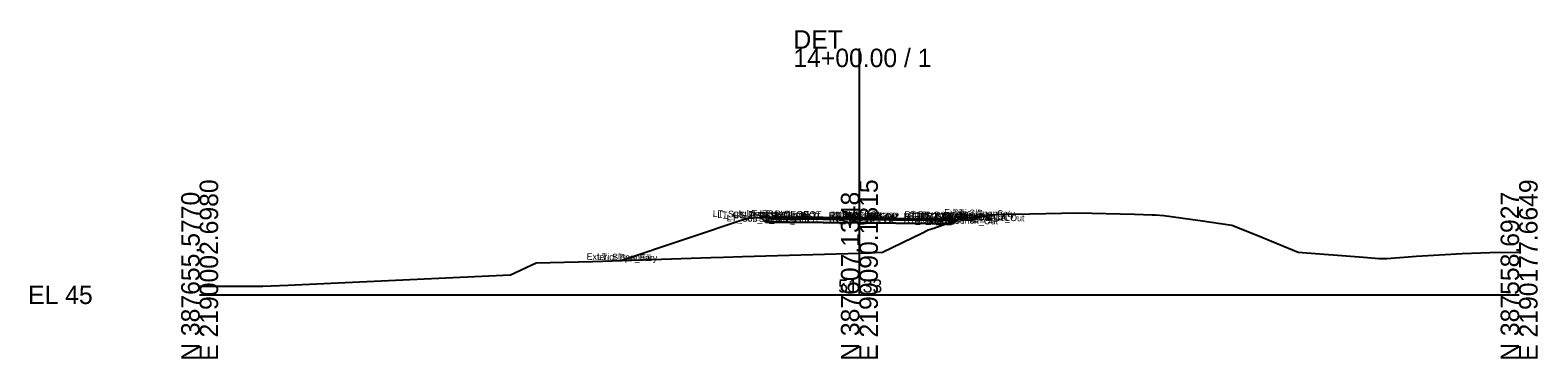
# Model space of a CAD drawing. Extents: x -26 to 1203, y -10 to 9543.
# Drawn here: x -25.7 to 202.8, y 3990.3 to 4040.1 of the extents above; entities that cross this region are included whole.
import ezdxf

# ---------------------------------------------------------------- set-up
doc = ezdxf.new("R2010")
doc.units = 0
for name, color, linetype in [('Default', 7, 'Continuous'), ('Exist Cross Section Cell', 7, 'Continuous'), ('Exist XS Center Line Elevation Label', 7, 'Continuous'), ('Exist XS Ground Line', 7, 'Continuous'), ('Prop CMT Pvmt Course 1', 7, 'Continuous'), ('Prop CMT Pvmt Course 2', 7, 'Continuous'), ('Prop CMT Pvmt Course 3', 7, 'Continuous'), ('Prop CMT Pvmt Surface', 7, 'Continuous'), ('Prop CMT Pvmt Surface Shoulder', 7, 'Continuous'), ('Prop CMT Shld Paved Course 1', 7, 'Continuous'), ('Prop CMT Shld Paved Course 2', 7, 'Continuous'), ('Prop CMT Shld Paved Course 3', 7, 'Continuous'), ('Prop CMT Slope Grass', 7, 'Continuous'), ('Prop CMT Subgrade Earthwork', 7, 'Continuous'), ('Scratch_Level_0', 7, 'Continuous')]:
    doc.layers.add(name, color=color, linetype=linetype)

msp = doc.modelspace()

# ---------------------------------------------------------------- linework, layer by layer
at = {"layer": 'Exist Cross Section Cell'}
for p, q in [((100, 4000), (100, 4037.28)), ((0, 4000), (100, 4000)), ((100, 4000), (200, 4000))]:
    msp.add_line(p, q, dxfattribs=at)
at = {"layer": 'Exist XS Ground Line'}
for p, q in [((111.15, 4010.06), (115.52, 4011.59)), ((115.52, 4011.59), (119.11, 4011.97)), ((119.11, 4011.97), (120.03, 4012.09)), ((120.03, 4012.09), (120.65, 4012.14)), ((120.65, 4012.14), (121.58, 4012.19)), ((121.58, 4012.19), (122.16, 4012.21)), ((122.16, 4012.21), (125.83, 4012.28)), ((125.83, 4012.28), (133.05, 4012.43)), ((133.05, 4012.43), (141.72, 4012.19)), ((141.72, 4012.19), (144.4, 4012.11)), ((144.4, 4012.11), (144.86, 4012.09)), ((144.86, 4012.09), (146.16, 4012.03)), ((146.16, 4012.03), (151.65, 4011.24)), ((151.65, 4011.24), (156.47, 4010.53)), ((103.49, 4006.44), (109.55, 4009.41)), ((109.55, 4009.41), (110.44, 4009.83)), ((110.44, 4009.83), (111.15, 4010.06)), ((156.47, 4010.53), (160.14, 4009.08)), ((160.14, 4009.08), (166.49, 4006.47)), ((82.27, 4005.78), (100, 4006.33)), ((100, 4006.33), (103.49, 4006.44)), ((166.49, 4006.47), (176.4, 4005.71)), ((184.44, 4005.86), (191.38, 4006.27)), ((191.38, 4006.27), (196.98, 4006.44)), ((196.98, 4006.44), (200, 4006.42)), ((47.1, 4003.02), (51.02, 4004.84)), ((51.02, 4004.84), (59.57, 4005.07)), ((59.57, 4005.07), (77.5, 4005.63)), ((77.5, 4005.63), (79.41, 4005.68)), ((79.41, 4005.68), (82.27, 4005.78)), ((176.4, 4005.71), (178.77, 4005.5)), ((178.77, 4005.5), (179.95, 4005.48)), ((179.95, 4005.48), (184.44, 4005.86)), ((13.35, 4001.46), (47.1, 4003.02)), ((0, 4001.32), (6.76, 4001.33)), ((6.76, 4001.33), (9.59, 4001.31)), ((9.59, 4001.31), (13.35, 4001.46))]:
    msp.add_line(p, q, dxfattribs=at)
at = {"layer": 'Prop CMT Pvmt Course 1'}
for points in [[(100, 4011.66), (89, 4011.74)], [(89, 4011.74), (89, 4011.49)], [(89, 4011.49), (100, 4011.41)], [(100, 4011.41), (100, 4011.66)], [(100, 4011.66), (111, 4011.57)], [(100, 4011.41), (100, 4011.66)], [(111, 4011.32), (100, 4011.41)], [(111, 4011.57), (111, 4011.32)]]:
    msp.add_lwpolyline(points, dxfattribs=at)
msp.add_lwpolyline([(100, 4011.41), (100, 4011.53), (100, 4011.53), (100, 4011.41)], close=True, dxfattribs=at)
msp.add_lwpolyline([(100, 4011.41), (100, 4011.53), (100, 4011.53), (100, 4011.41)], close=True, dxfattribs=at)
at = {"layer": 'Prop CMT Pvmt Course 2'}
for points in [[(89, 4011.49), (100, 4011.41)], [(100, 4011.41), (89, 4011.49)], [(89, 4011.49), (89, 4011.49)], [(100, 4011.41), (100, 4011.41)], [(111, 4011.32), (100, 4011.41)], [(100, 4011.41), (100, 4011.41)], [(100, 4011.41), (111, 4011.32)], [(111, 4011.32), (111, 4011.32)]]:
    msp.add_lwpolyline(points, dxfattribs=at)
at = {"layer": 'Prop CMT Pvmt Course 3'}
for points in [[(100, 4011.41), (89, 4011.49)], [(89, 4011.49), (89, 4010.99)], [(89, 4010.99), (100, 4010.91)], [(100, 4010.91), (100, 4011.41)], [(100, 4011.41), (111, 4011.32)], [(100, 4010.91), (100, 4011.41)], [(111, 4010.82), (100, 4010.91)], [(111, 4011.32), (111, 4010.82)]]:
    msp.add_lwpolyline(points, dxfattribs=at)
at = {"layer": 'Prop CMT Pvmt Surface'}
for points in [[(100, 4011.66), (89, 4011.74)], [(100, 4011.66), (111, 4011.57)]]:
    msp.add_lwpolyline(points, dxfattribs=at)
at = {"layer": 'Prop CMT Pvmt Surface Shoulder'}
for points in [[(89, 4011.74), (87, 4011.76)], [(111, 4011.57), (113, 4011.56)]]:
    msp.add_lwpolyline(points, dxfattribs=at)
at = {"layer": 'Prop CMT Shld Paved Course 1'}
for points in [[(89, 4011.74), (87, 4011.76), (86.75, 4011.51)], [(86.75, 4011.51), (89, 4011.49)], [(89, 4011.49), (89, 4011.74)], [(111, 4011.57), (113, 4011.56), (113.25, 4011.31)], [(111, 4011.32), (111, 4011.57)], [(113.25, 4011.31), (111, 4011.32)]]:
    msp.add_lwpolyline(points, dxfattribs=at)
at = {"layer": 'Prop CMT Shld Paved Course 2'}
for points in [[(89, 4011.49), (86.75, 4011.51)], [(86.75, 4011.51), (86.75, 4011.51)], [(86.75, 4011.51), (89, 4011.49)], [(89, 4011.49), (89, 4011.49)], [(111, 4011.32), (113.25, 4011.31)], [(113.25, 4011.31), (111, 4011.32)], [(111, 4011.32), (111, 4011.32)], [(113.25, 4011.31), (113.25, 4011.31)]]:
    msp.add_lwpolyline(points, dxfattribs=at)
at = {"layer": 'Prop CMT Shld Paved Course 3'}
for points in [[(89, 4011.49), (86.75, 4011.51), (86.25, 4011.51), (85.76, 4011.02)], [(85.76, 4011.02), (89, 4010.99)], [(89, 4010.99), (89, 4011.49)], [(111, 4011.32), (113.25, 4011.31), (113.75, 4011.3), (114.26, 4010.8)], [(111, 4010.82), (111, 4011.32)], [(114.26, 4010.8), (111, 4010.82)]]:
    msp.add_lwpolyline(points, dxfattribs=at)
at = {"layer": 'Prop CMT Slope Grass'}
for points in [[(87, 4011.76), (83, 4011.55), (63.99, 4005.21)], [(113, 4011.56), (117, 4011.29), (117.01, 4011.28), (118.19, 4011.87)]]:
    msp.add_lwpolyline(points, dxfattribs=at)
at = {"layer": 'Prop CMT Subgrade Earthwork'}
for points in [[(85.76, 4011.02), (85.11, 4011.66)], [(89, 4010.99), (85.76, 4011.02)], [(100, 4010.91), (89, 4010.99)], [(100, 4010.91), (111, 4010.82)], [(111, 4010.82), (114.26, 4010.8)], [(114.26, 4010.8), (114.89, 4011.43)]]:
    msp.add_lwpolyline(points, dxfattribs=at)

# ---------------------------------------------------------------- texts
at = {"layer": 'Default'}
msp.add_text('-', height=0.0001, dxfattribs=at).set_placement((0, 4000))
at = {"layer": 'Exist Cross Section Cell'}
for s, p in [('DET', (90, 4037.28)), ('14+00.00 / 1', (90, 4034.48)), ('EL 45', (-26, 3998.6))]:
    msp.add_text(s, height=2.8, dxfattribs=at).set_placement(p)
for s, p in [('N 387655.5770', (0, 3990)), ('E 2190002.6980', (2.8, 3990)), ('N 387607.1348', (100, 3990)), ('E 2190090.1815', (102.8, 3990)), ('N 387558.6927', (200, 3990)), ('E 2190177.6649', (202.8, 3990))]:
    msp.add_text(s, height=2.8, rotation=90, dxfattribs=at).set_placement(p)
at = {"layer": 'Exist XS Center Line Elevation Label'}
msp.add_text('51.33', height=2, dxfattribs=at).set_placement((96.78, 4000.33))
at = {"layer": 'Scratch_Level_0'}
for s, p in [('LT_Sub_Trench_Out_DLT', (77.77, 4011.8)), ('LT_GS_OS_CTL', (78.46, 4011.64)), ('LT_Sub_Trench_Out', (79.87, 4011.13)), ('LT_PS3_Shelf_Out', (80.91, 4011.62)), ('LT_PS3_OEOP', (82.54, 4011.59)), ('LT_PS2_OEOP', (82.54, 4011.59)), ('LT_PS1_OEOP', (82.91, 4011.84)), ('LT_PV2_OEOT', (84.75, 4011.57)), ('LT_PV3_OEOT', (84.75, 4011.57)), ('LT_Sub_OEOT', (84.77, 4011.07)), ('LT_PV1_OEOT', (84.87, 4011.82)), ('RT_PV2_OEEOP', (95.33, 4011.5)), ('RT_PV3_OEEOP', (95.33, 4011.5)), ('RT_Sub_OEEOP', (95.36, 4011)), ('LT_PV2_OEEOP', (95.39, 4011.5)), ('LT_PV3_OEEOP', (95.39, 4011.5)), ('LT_Sub_OEEOP', (95.42, 4011)), ('RT_PV1_OEEOP', (95.45, 4011.62)), ('LT_PV1_OEEOP', (95.51, 4011.62)), ('RT_PV2_IEEOP', (95.71, 4011.49)), ('LT_PV2_IEEOP', (95.77, 4011.49)), ('RT_PV1_IEEOP', (95.83, 4011.61)), ('LT_PV1_IEEOP', (95.89, 4011.61)), ('PV2_PGL', (97.35, 4011.46)), ('PV1_PGL', (97.47, 4011.71)), ('RT_PV3_OEOT', (106.69, 4011.41)), ('RT_PV2_OEOT', (106.69, 4011.41)), ('RT_Sub_OEOT', (106.71, 4010.91)), ('RT_PV1_OEOT', (106.81, 4011.65)), ('RT_Sub_Trench_Out_DLT', (107.48, 4011.57)), ('RT_Sub_Trench_Out', (108.31, 4010.91)), ('RT_PS3_Shelf_Out', (108.35, 4011.41)), ('RT_PS1_OEOP', (108.85, 4011.64)), ('RT_PS3_OEOP', (108.98, 4011.39)), ('RT_PS2_OEOP', (108.98, 4011.39)), ('RT_SS_Ditch_Base_Out', (110.21, 4011.42)), ('RT_GS_OS_CTL', (112.41, 4011.38)), ('Exterior Boundary', (112.85, 4011.98)), ('RT_Slope_Cut', (114.13, 4011.95)), ('Exterior Boundary', (58.65, 4005.31)), ('LT_Slope_Fill', (60.22, 4005.28))]:
    msp.add_text(s, height=1, rotation=358.8836, dxfattribs=at).set_placement(p)

doc.saveas('drawing.dxf')
